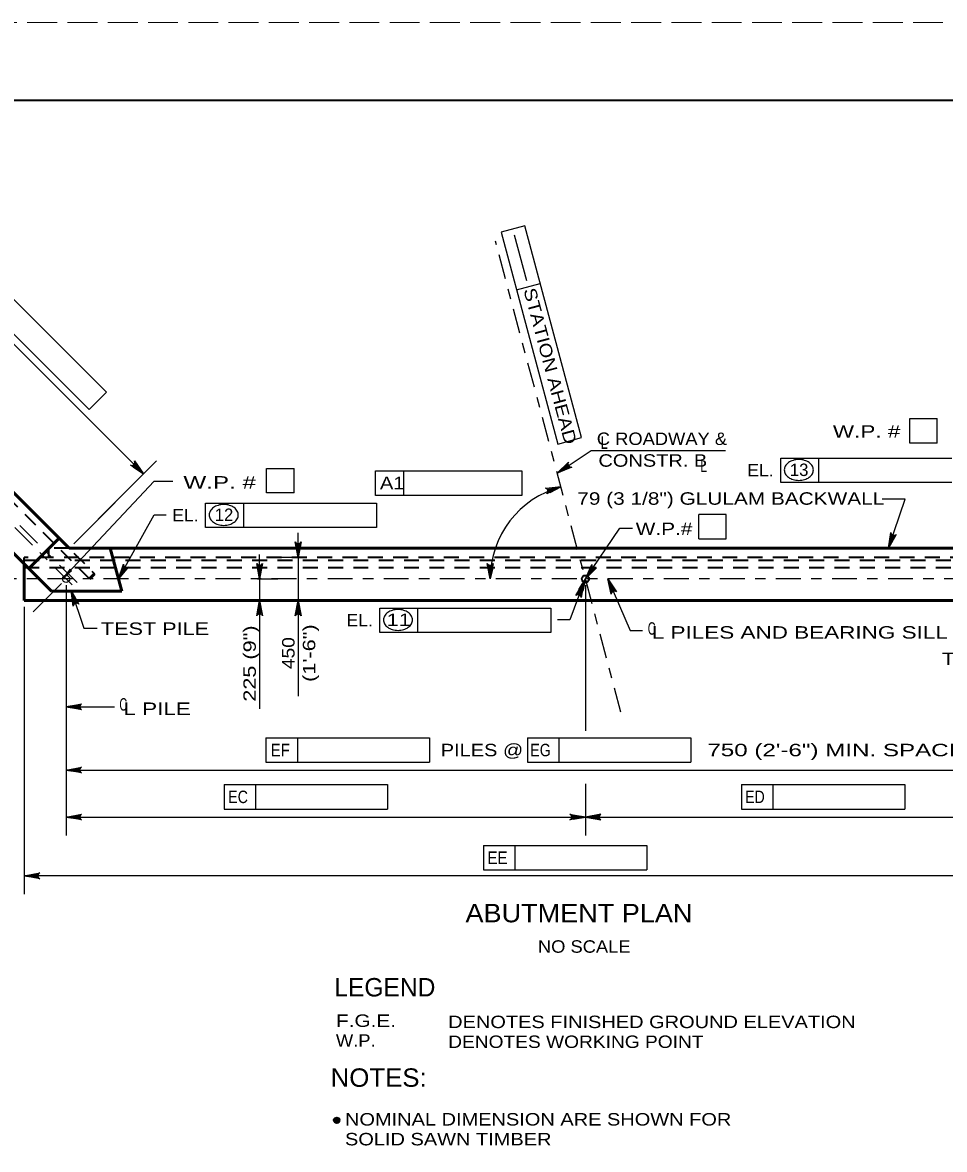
# Model space of a CAD drawing. Extents: x -6.4 to 73.1, y -66 to 0.
# Drawn here: x 42.06 to 50.94, y -10.86 to 0 of the extents above; entities that cross this region are included whole.
import ezdxf
from ezdxf.enums import TextEntityAlignment as Align

# ---------------------------------------------------------------- set-up
doc = ezdxf.new("R2010")
doc.units = 0
doc.header["$LTSCALE"] = 0.048
for name, pattern in [('DOT_DASHED', [7.7, 5, -1.2, 0.3, -1.2]), ('LONG_DASHED', [7.5, 6, -1.5]), ('MEDIUM_DASHED', [4.5, 3, -1.5])]:
    doc.linetypes.add(name, pattern=pattern)
for name, color, linetype, lineweight in [('1', 7, 'Continuous', 13), ('2', 7, 'Continuous', 53), ('3', 7, 'Continuous', 35), ('4', 7, 'Continuous', 25), ('5', 7, 'Continuous', 25), ('6', 7, 'DOT_DASHED', 25), ('63', 7, 'LONG_DASHED', 13)]:
    doc.layers.add(name, color=color, linetype=linetype, lineweight=lineweight)

msp = doc.modelspace()

# ---------------------------------------------------------------- hatches: boundary and pattern name
at = {"layer": '4'}
for points in [[(43.15342, -4.25192), (43.12558, -4.27975), (43.223, -4.34933)], [(47.29833, -4.26058), (47.32025, -4.29333), (47.21108, -4.3425)], [(47.13792, -4.53175), (47.12533, -4.49442), (47.2435, -4.47525)], [(50.40383, -5.06467), (50.451, -4.956), (50.43242, -4.94967)], [(44.69458, -5.03517), (44.734, -5.03517), (44.71433, -5.15325)], [(42.44258, -5.36), (42.53067, -5.28067), (42.51633, -5.26725)], [(43.021, -5.25075), (43.05542, -5.26975), (42.98108, -5.36358)], [(44.32292, -5.24183), (44.36225, -5.24183), (44.34258, -5.36)], [(46.55258, -5.24083), (46.59183, -5.24342), (46.56458, -5.36)], [(47.48233, -5.36), (47.55692, -5.26783), (47.54058, -5.25683)], [(47.4565, -5.47692), (47.41992, -5.46217), (47.48233, -5.36)], [(47.69683, -5.36), (47.735, -5.47225), (47.753, -5.46433)], [(42.52558, -5.47133), (42.55425, -5.58633), (42.57292, -5.58)], [(44.32292, -5.68475), (44.36225, -5.68475), (44.34258, -5.56667)], [(44.69458, -5.68475), (44.734, -5.68475), (44.71433, -5.56667)], [(42.59633, -6.61167), (42.59633, -6.57233), (42.47825, -6.592)], [(42.59633, -7.18158), (42.59633, -7.221), (42.47825, -7.20125)], [(42.59633, -7.63492), (42.59633, -7.67425), (42.47825, -7.65458)], [(47.36417, -7.63492), (47.36417, -7.67425), (47.48233, -7.65458)], [(47.60042, -7.63492), (47.60042, -7.67425), (47.48233, -7.65458)], [(42.19233, -8.20067), (42.19233, -8.24008), (42.07425, -8.22042)]]:
    msp.add_hatch(color=256, dxfattribs=at).paths.add_polyline_path(points)

# ---------------------------------------------------------------- linework, layer by layer
at = {"layer": '1', "lineweight": 35}
msp.add_lwpolyline([(35.75, -21.25), (67.25, -21.25), (67.25, -0.75), (35.75, -0.75)], close=True, dxfattribs=at)
at = {"layer": '2'}
for p, q in [((42.50767, -5.06467), (41.70775, -4.26483)), ((42.33642, -5.47808), (41.4155, -4.55708)), ((42.41025, -4.96725), (42.11792, -5.25958)), ((52.37042, -5.06467), (42.50767, -5.06467)), ((42.90358, -5.06467), (43.01383, -5.47808)), ((42.07425, -5.56667), (42.07425, -5.21583)), ((42.70317, -5.36), (42.75192, -5.31125)), ((43.01383, -5.47808), (42.33642, -5.47808)), ((52.84975, -5.56667), (42.07425, -5.56667))]:
    msp.add_line(p, q, dxfattribs=at)
at = {"layer": '3', "linetype": 'MEDIUM_DASHED'}
for p, q in [((42.70317, -5.36), (41.65908, -4.3135)), ((42.31217, -5.15325), (42.31217, -5.06467)), ((42.50767, -5.06467), (42.31217, -5.06467)), ((52.84975, -5.15325), (42.07425, -5.15325)), ((42.07425, -5.17967), (52.84975, -5.17967)), ((42.55367, -5.11067), (42.75192, -5.31125)), ((42.07425, -5.24858), (52.84975, -5.24858))]:
    msp.add_line(p, q, dxfattribs=at)
at = {"layer": '3'}
msp.add_line((42.07425, -5.21583), (42.07425, -5.15325), dxfattribs=at)
msp.add_circle((47.48232, -5.35998), 0.03402, dxfattribs=at)
at = {"layer": '4'}
for p, q in [((43.223, -4.34933), (40.84933, -1.97567)), ((46.89733, -1.9575), (46.66917, -2.01867)), ((46.66917, -2.01867), (47.21625, -4.06042)), ((46.91658, -2.48725), (46.79933, -2.04958)), ((47.44442, -3.99925), (46.89742, -1.9575)), ((41.6635, -2.35983), (42.86617, -3.5625)), ((41.4965, -2.52683), (42.69908, -3.7295)), ((46.81833, -2.57525), (47.0465, -2.51408)), ((42.86617, -3.5625), (42.69908, -3.7295)), ((50.8725, -4.05125), (50.8725, -3.81508)), ((47.21625, -4.06042), (47.44442, -3.99925)), ((47.21108, -4.34258), (47.53908, -4.12342)), ((47.53908, -4.12342), (48.831, -4.12342)), ((50.8725, -4.05125), (50.60883, -4.05125)), ((42.55117, -5.02117), (43.34825, -4.22408)), ((49.36392, -4.19658), (51.01225, -4.19658)), ((49.36392, -4.43283), (49.36392, -4.19658)), ((49.73075, -4.43283), (49.73075, -4.19658)), ((44.41058, -4.29517), (44.67425, -4.29517)), ((44.67425, -4.53142), (44.67425, -4.29517)), ((45.45883, -4.319), (46.87083, -4.319)), ((45.45883, -4.55525), (45.45883, -4.319)), ((45.73258, -4.55525), (45.73258, -4.319)), ((46.87083, -4.319), (46.87083, -4.55525)), ((51.01225, -4.43283), (49.36392, -4.43283)), ((42.55117, -5.02117), (43.01925, -4.55308)), ((46.87083, -4.55525), (45.45883, -4.55525)), ((43.82217, -4.62983), (45.47058, -4.62983)), ((43.82217, -4.86608), (43.82217, -4.62983)), ((44.189, -4.86608), (44.189, -4.62983)), ((45.47058, -4.62983), (45.47058, -4.86608)), ((42.98258, -5.36092), (43.32508, -4.74142)), ((43.32508, -4.74142), (43.44325, -4.74142)), ((48.839, -4.73858), (48.57533, -4.73858)), ((48.57533, -4.97483), (48.57533, -4.73858)), ((48.839, -4.97483), (48.839, -4.73858)), ((45.47058, -4.86608), (43.82217, -4.86608)), ((44.71433, -5.03517), (44.71433, -4.91708)), ((48.57533, -4.97483), (48.839, -4.97483)), ((44.34258, -5.24183), (44.34258, -5.12375)), ((44.6915, -5.15325), (44.53717, -5.15325)), ((44.71433, -5.15325), (44.71433, -5.56667)), ((42.43475, -5.4035), (42.16058, -5.67758)), ((42.47825, -5.4215), (42.47825, -7.83175)), ((44.32258, -5.36), (44.51975, -5.36)), ((44.34258, -5.36), (44.34258, -5.56667)), ((47.46758, -5.39067), (47.33242, -5.75308)), ((47.48233, -5.4215), (47.48233, -6.82475)), ((42.07425, -5.62817), (42.07425, -8.39758)), ((44.32258, -5.56667), (44.51975, -5.56667)), ((44.6915, -5.56667), (44.53717, -5.56667)), ((45.50117, -5.64158), (47.1495, -5.64158)), ((45.50117, -5.87775), (45.50117, -5.64158)), ((45.868, -5.87775), (45.868, -5.64158)), ((47.1495, -5.64158), (47.1495, -5.87775)), ((44.34258, -5.68475), (44.34258, -6.61192)), ((44.71433, -5.68475), (44.71433, -6.48883)), ((47.33242, -5.75308), (47.21425, -5.75308)), ((47.1495, -5.87775), (45.50117, -5.87775)), ((42.47825, -6.592), (42.94283, -6.592)), ((44.40375, -6.89058), (44.40375, -7.12683)), ((44.40375, -6.89058), (45.9785, -6.89058)), ((44.70617, -6.89058), (44.70617, -7.12683)), ((45.9785, -6.89058), (45.9785, -7.12683)), ((46.92433, -6.89058), (48.49917, -6.89058)), ((46.92433, -6.89058), (46.92433, -7.12683)), ((47.22675, -6.89058), (47.22675, -7.12683)), ((48.49917, -6.89058), (48.49917, -7.12683)), ((44.40375, -7.12683), (45.9785, -7.12683)), ((46.92433, -7.12683), (48.49917, -7.12683)), ((42.47825, -7.20125), (52.39958, -7.20133)), ((44.00158, -7.34175), (45.57642, -7.34175)), ((44.00158, -7.34175), (44.00158, -7.578)), ((44.304, -7.34175), (44.304, -7.578)), ((45.57642, -7.34175), (45.57642, -7.578)), ((47.48233, -7.334), (47.48233, -7.83175)), ((48.98658, -7.34175), (50.56142, -7.34175)), ((48.98658, -7.34175), (48.98658, -7.578)), ((49.28908, -7.34175), (49.28908, -7.578)), ((50.56142, -7.34175), (50.56142, -7.578)), ((44.00158, -7.578), (45.57642, -7.578)), ((48.98658, -7.578), (50.56142, -7.578)), ((42.47825, -7.65458), (47.36417, -7.65458)), ((47.60042, -7.65458), (52.39958, -7.65458)), ((46.49892, -7.92767), (48.07375, -7.92767)), ((46.49892, -7.92767), (46.49892, -8.16383)), ((46.80142, -7.92767), (46.80142, -8.16383)), ((48.07375, -7.92767), (48.07375, -8.16383)), ((52.84975, -8.22042), (42.07425, -8.22042)), ((46.49892, -8.16383), (48.07375, -8.16383))]:
    msp.add_line(p, q, dxfattribs=at)
at = {"layer": '4', "linetype": 'DOT_DASHED'}
for p, q in [((42.53525, -5.417), (41.53792, -4.41967)), ((42.58425, -5.39617), (41.59467, -4.40667)), ((53.33858, -5.36), (41.53183, -5.36))]:
    msp.add_line(p, q, dxfattribs=at)
at = {"layer": '4'}
for points in [[(50.60883, -4.05125), (50.60883, -3.81508), (50.8725, -3.81508)], [(43.223, -4.34933), (43.09775, -4.26367), (43.1115, -4.26617), (43.12283, -4.26325), (43.13108, -4.25742), (43.13692, -4.24917), (43.13983, -4.23783), (43.13733, -4.22408), (43.223, -4.34933), (43.13983, -4.23783), (43.13692, -4.24917), (43.223, -4.34933), (43.13108, -4.25742), (43.12283, -4.26325), (43.223, -4.34933), (43.1115, -4.26617)], [(44.67425, -4.53142), (44.41058, -4.53142), (44.41058, -4.29517)], [(47.21108, -4.34258), (47.31958, -4.2365), (47.31442, -4.2495), (47.31508, -4.26108), (47.31917, -4.27033), (47.32617, -4.27775), (47.33667, -4.28275), (47.35058, -4.283), (47.21108, -4.34258), (47.33667, -4.28275), (47.32617, -4.27775), (47.21108, -4.34258), (47.31917, -4.27033), (47.31508, -4.26108), (47.21108, -4.34258), (47.31442, -4.2495)], [(42.44258, -5.36), (43.32783, -4.41908), (43.50767, -4.41908)], [(47.24625, -4.4745), (47.10925, -4.53967), (47.11833, -4.529), (47.1215, -4.51783), (47.12058, -4.50775), (47.11633, -4.4985), (47.10808, -4.49033), (47.09492, -4.48558), (47.24625, -4.4745), (47.10808, -4.49033), (47.11633, -4.4985), (47.24625, -4.4745), (47.12058, -4.50775), (47.1215, -4.51783), (47.24625, -4.4745), (47.11833, -4.529)], [(50.40383, -5.06467), (50.56333, -4.59325), (50.34317, -4.59325)], [(47.48233, -5.36), (47.81508, -4.87083), (47.936, -4.87083)], [(50.40383, -5.06467), (50.42517, -4.91442), (50.429, -4.92792), (50.43658, -4.93667), (50.4455, -4.9415), (50.4555, -4.94308), (50.46692, -4.94067), (50.47808, -4.93233), (50.40383, -5.06467), (50.46692, -4.94067), (50.4555, -4.94308), (50.40383, -5.06467), (50.4455, -4.9415), (50.43658, -4.93667), (50.40383, -5.06467), (50.429, -4.92792)], [(44.71433, -5.15325), (44.68633, -5.00408), (44.69433, -5.01558), (44.70433, -5.0215), (44.71433, -5.02325), (44.72433, -5.0215), (44.73433, -5.01558), (44.74233, -5.00408), (44.71433, -5.15325), (44.73433, -5.01558), (44.72433, -5.0215), (44.71433, -5.15325), (44.71433, -5.02325), (44.70433, -5.0215), (44.71433, -5.15325), (44.69433, -5.01558)], [(44.34258, -5.36), (44.31458, -5.21083), (44.32258, -5.22233), (44.33258, -5.22825), (44.34258, -5.23), (44.35258, -5.22825), (44.36258, -5.22233), (44.37058, -5.21083), (44.34258, -5.36), (44.36258, -5.22233), (44.35258, -5.22825), (44.34258, -5.36), (44.34258, -5.23), (44.33258, -5.22825), (44.34258, -5.36), (44.32258, -5.22233)], [(46.56458, -5.36), (46.53658, -5.21083), (46.54458, -5.22233), (46.55458, -5.22825), (46.56458, -5.23), (46.57458, -5.22825), (46.58458, -5.22233), (46.59258, -5.21083), (46.56458, -5.36), (46.58458, -5.22233), (46.57458, -5.22825), (46.56458, -5.36), (46.56458, -5.23), (46.55458, -5.22825), (46.56458, -5.36), (46.54458, -5.22233)], [(42.98258, -5.36092), (43.03025, -5.21683), (43.03167, -5.23075), (43.03758, -5.24083), (43.0455, -5.24717), (43.05508, -5.2505), (43.06667, -5.25017), (43.07925, -5.24392), (42.98258, -5.36092), (43.06667, -5.25017), (43.05508, -5.2505), (42.98258, -5.36092), (43.0455, -5.24717), (43.03758, -5.24083), (42.98258, -5.36092), (43.03167, -5.23075)], [(47.48233, -5.36), (47.54308, -5.221), (47.54325, -5.23492), (47.54817, -5.2455), (47.55542, -5.2525), (47.56467, -5.25675), (47.57625, -5.25742), (47.58933, -5.25242), (47.48233, -5.36), (47.57625, -5.25742), (47.56467, -5.25675), (47.48233, -5.36), (47.55542, -5.2525), (47.54817, -5.2455), (47.48233, -5.36), (47.54325, -5.23492)], [(47.46758, -5.39067), (47.44167, -5.54017), (47.43825, -5.52658), (47.43092, -5.51758), (47.42217, -5.5125), (47.41217, -5.51058), (47.40075, -5.51267), (47.38925, -5.52067), (47.46758, -5.39067), (47.40075, -5.51267), (47.41217, -5.51058), (47.46758, -5.39067), (47.42217, -5.5125), (47.43092, -5.51758), (47.46758, -5.39067), (47.43825, -5.52658)], [(47.69683, -5.36), (47.91358, -5.85817), (48.03158, -5.85817)], [(47.69683, -5.36), (47.782, -5.48558), (47.77008, -5.47825), (47.75858, -5.47675), (47.74867, -5.47917), (47.74025, -5.48475), (47.73342, -5.49417), (47.73067, -5.50792), (47.69683, -5.36), (47.73342, -5.49417), (47.74025, -5.48475), (47.69683, -5.36), (47.74867, -5.47917), (47.75858, -5.47675), (47.69683, -5.36), (47.77008, -5.47825)], [(42.52558, -5.47133), (42.64967, -5.83608), (42.7785, -5.83608)], [(42.52558, -5.47133), (42.60008, -5.6035), (42.58883, -5.59517), (42.5775, -5.59283), (42.56742, -5.59442), (42.5585, -5.59925), (42.551, -5.60808), (42.54717, -5.6215), (42.52558, -5.47133), (42.551, -5.60808), (42.5585, -5.59925), (42.52558, -5.47133), (42.56742, -5.59442), (42.5775, -5.59283), (42.52558, -5.47133), (42.58883, -5.59517)], [(44.34258, -5.56667), (44.37058, -5.71583), (44.36258, -5.70433), (44.35258, -5.69842), (44.34258, -5.69667), (44.33258, -5.69842), (44.32258, -5.70433), (44.31458, -5.71583), (44.34258, -5.56667), (44.32258, -5.70433), (44.33258, -5.69842), (44.34258, -5.56667), (44.34258, -5.69667), (44.35258, -5.69842), (44.34258, -5.56667), (44.36258, -5.70433)], [(44.71433, -5.56667), (44.74233, -5.71583), (44.73433, -5.70433), (44.72433, -5.69842), (44.71433, -5.69667), (44.70433, -5.69842), (44.69433, -5.70433), (44.68633, -5.71583), (44.71433, -5.56667), (44.69433, -5.70433), (44.70433, -5.69842), (44.71433, -5.56667), (44.71433, -5.69667), (44.72433, -5.69842), (44.71433, -5.56667), (44.73433, -5.70433)], [(42.47825, -6.592), (42.62742, -6.564), (42.61592, -6.572), (42.61, -6.582), (42.60825, -6.592), (42.61, -6.602), (42.61592, -6.612), (42.62742, -6.62), (42.47825, -6.592), (42.61592, -6.612), (42.61, -6.602), (42.47825, -6.592), (42.60825, -6.592), (42.61, -6.582), (42.47825, -6.592), (42.61592, -6.572)], [(42.47825, -7.20125), (42.62742, -7.17325), (42.61592, -7.18125), (42.61, -7.19125), (42.60825, -7.20125), (42.61, -7.21125), (42.61592, -7.22125), (42.62742, -7.22925), (42.47825, -7.20125), (42.61592, -7.22125), (42.61, -7.21125), (42.47825, -7.20125), (42.60825, -7.20125), (42.61, -7.19125), (42.47825, -7.20125), (42.61592, -7.18125)], [(42.47825, -7.65458), (42.62742, -7.62658), (42.61592, -7.63458), (42.61, -7.64458), (42.60825, -7.65458), (42.61, -7.66458), (42.61592, -7.67458), (42.62742, -7.68258), (42.47825, -7.65458), (42.61592, -7.67458), (42.61, -7.66458), (42.47825, -7.65458), (42.60825, -7.65458), (42.61, -7.64458), (42.47825, -7.65458), (42.61592, -7.63458)], [(47.48233, -7.65458), (47.33317, -7.68258), (47.34467, -7.67458), (47.35058, -7.66458), (47.35233, -7.65458), (47.35058, -7.64458), (47.34467, -7.63458), (47.33317, -7.62658), (47.48233, -7.65458), (47.34467, -7.63458), (47.35058, -7.64458), (47.48233, -7.65458), (47.35233, -7.65458), (47.35058, -7.66458), (47.48233, -7.65458), (47.34467, -7.67458)], [(47.48233, -7.65458), (47.6315, -7.68258), (47.62, -7.67458), (47.61408, -7.66458), (47.61233, -7.65458), (47.61408, -7.64458), (47.62, -7.63458), (47.6315, -7.62658), (47.48233, -7.65458), (47.62, -7.63458), (47.61408, -7.64458), (47.48233, -7.65458), (47.61233, -7.65458), (47.61408, -7.66458), (47.48233, -7.65458), (47.62, -7.67458)], [(42.07425, -8.22042), (42.22342, -8.19242), (42.21192, -8.20042), (42.206, -8.21042), (42.20425, -8.22042), (42.206, -8.23042), (42.21192, -8.24042), (42.22342, -8.24842), (42.07425, -8.22042), (42.21192, -8.24042), (42.206, -8.23042), (42.07425, -8.22042), (42.20425, -8.22042), (42.206, -8.21042), (42.07425, -8.22042), (42.21192, -8.20042)]]:
    msp.add_lwpolyline(points, dxfattribs=at)
for points in [[(43.15342, -4.25192), (43.12558, -4.27975), (43.223, -4.34933)], [(47.29833, -4.26058), (47.32025, -4.29333), (47.21108, -4.3425)], [(47.13792, -4.53175), (47.12533, -4.49442), (47.2435, -4.47525)], [(50.40383, -5.06467), (50.451, -4.956), (50.43242, -4.94967)], [(44.69458, -5.03517), (44.734, -5.03517), (44.71433, -5.15325)], [(42.44258, -5.36), (42.53067, -5.28067), (42.51633, -5.26725)], [(43.021, -5.25075), (43.05542, -5.26975), (42.98108, -5.36358)], [(44.32292, -5.24183), (44.36225, -5.24183), (44.34258, -5.36)], [(46.55258, -5.24083), (46.59183, -5.24342), (46.56458, -5.36)], [(47.48233, -5.36), (47.55692, -5.26783), (47.54058, -5.25683)], [(47.4565, -5.47692), (47.41992, -5.46217), (47.48233, -5.36)], [(47.69683, -5.36), (47.735, -5.47225), (47.753, -5.46433)], [(42.52558, -5.47133), (42.55425, -5.58633), (42.57292, -5.58)], [(44.32292, -5.68475), (44.36225, -5.68475), (44.34258, -5.56667)], [(44.69458, -5.68475), (44.734, -5.68475), (44.71433, -5.56667)], [(42.59633, -6.61167), (42.59633, -6.57233), (42.47825, -6.592)], [(42.59633, -7.18158), (42.59633, -7.221), (42.47825, -7.20125)], [(42.59633, -7.63492), (42.59633, -7.67425), (42.47825, -7.65458)], [(47.36417, -7.63492), (47.36417, -7.67425), (47.48233, -7.65458)], [(47.60042, -7.63492), (47.60042, -7.67425), (47.48233, -7.65458)], [(42.19233, -8.20067), (42.19233, -8.24008), (42.07425, -8.22042)]]:
    msp.add_lwpolyline(points, close=True, dxfattribs=at)
msp.add_circle((42.47824, -5.35998), 0.03402, dxfattribs=at)
at = {"layer": '4', "lineweight": 35}
for radius in [0.02667, 0.02, 0.01333, 0.00667]:
    msp.add_circle((45.08607, -10.57529), radius, dxfattribs=at)
at = {"layer": '4'}
for centre, radius, start, end in [((49.5252, -4.35842), 0.14646, 106.53583, 125.63164), ((49.53897, -4.40482), 0.19487, 90, 106.53583), ((49.53897, -4.40482), 0.19487, 73.46417, 90), ((49.55275, -4.35842), 0.14646, 54.36836, 73.46417), ((49.47192, -4.31041), 0.07309, 149.97668, 180), ((49.47192, -4.31041), 0.07309, 180, 210.02332), ((49.50413, -4.32903), 0.1103, 125.63164, 149.97668), ((49.57382, -4.32903), 0.1103, 30.02332, 54.36836), ((49.60603, -4.31041), 0.07309, 0, 30.02332), ((49.60603, -4.31041), 0.07309, 329.97668, 0), ((49.50413, -4.2918), 0.1103, 210.02332, 234.36836), ((49.5252, -4.26241), 0.14646, 234.36836, 253.46417), ((49.53897, -4.216), 0.19487, 253.46417, 270), ((49.53897, -4.216), 0.19487, 270, 286.53583), ((49.55275, -4.26241), 0.14646, 286.53583, 305.63164), ((49.57382, -4.2918), 0.1103, 305.63164, 329.97668), ((47.48056, -5.35999), 0.91598, 104.82219, 180.00094), ((43.98348, -4.7917), 0.14646, 106.53583, 125.63164), ((43.99726, -4.83811), 0.19487, 90, 106.53583), ((43.99726, -4.83811), 0.19487, 73.46417, 90), ((44.01104, -4.7917), 0.14646, 54.36836, 73.46417), ((43.93021, -4.74369), 0.07309, 149.97668, 180), ((43.93021, -4.74369), 0.07309, 180, 210.02332), ((43.96242, -4.76231), 0.1103, 125.63164, 149.97668), ((44.03211, -4.76231), 0.1103, 30.02332, 54.36836), ((44.06432, -4.74369), 0.07309, 0, 30.02332), ((44.06432, -4.74369), 0.07309, 329.97668, 0), ((43.96242, -4.72508), 0.1103, 210.02332, 234.36836), ((43.98348, -4.69569), 0.14646, 234.36836, 253.46417), ((43.99726, -4.64928), 0.19487, 253.46417, 270), ((43.99726, -4.64928), 0.19487, 270, 286.53583), ((44.01104, -4.69569), 0.14646, 286.53583, 305.63164), ((44.03211, -4.72508), 0.1103, 305.63164, 329.97668), ((45.60919, -5.75538), 0.07309, 149.97668, 180), ((45.6414, -5.774), 0.1103, 125.63164, 149.97668), ((45.66247, -5.80339), 0.14646, 106.53583, 125.63164), ((45.67624, -5.8498), 0.19487, 90, 106.53583), ((45.67624, -5.8498), 0.19487, 73.46417, 90), ((45.69002, -5.80339), 0.14646, 54.36836, 73.46417), ((45.71109, -5.774), 0.1103, 30.02332, 54.36836), ((45.7433, -5.75538), 0.07309, 0, 30.02332), ((45.60919, -5.75538), 0.07309, 180, 210.02332), ((45.6414, -5.73677), 0.1103, 210.02332, 234.36836), ((45.66247, -5.70738), 0.14646, 234.36836, 253.46417), ((45.67624, -5.66097), 0.19487, 253.46417, 270), ((45.67624, -5.66097), 0.19487, 270, 286.53583), ((45.69002, -5.70738), 0.14646, 286.53583, 305.63164), ((45.71109, -5.73677), 0.1103, 305.63164, 329.97668), ((45.7433, -5.75538), 0.07309, 329.97668, 0)]:
    msp.add_arc(centre, radius, start, end, dxfattribs=at)
at = {"layer": '6'}
msp.add_line((47.82483, -6.64492), (46.61467, -2.10533), dxfattribs=at)
at = {"layer": '63'}
msp.add_lwpolyline([(34, -22), (68, -22), (68, 0), (34, 0)], close=True, dxfattribs=at)

# ---------------------------------------------------------------- texts
at = {"layer": '4', "width": 1.2}
msp.add_text('STATION AHEAD', height=0.12, rotation=285, dxfattribs=at).set_placement((47.08499, -3.32451), align=Align.CENTER)
at = {"layer": '4'}
for s, height, width, p in [('W.P. #', 0.12, 1.35, (50.19204, -3.99942)), ('W.P. # ', 0.12, 1.45, (43.99012, -4.49)), ('A1', 0.12, 1.2, (45.62037, -4.49583)), ('11', 0.12, 1.3, (45.68354, -5.81383)), ('PILES @', 0.12, 1.2, (46.48554, -7.06875)), ('EG', 0.12, 0.85, (47.04992, -7.06875)), ('EF', 0.12, 0.9, (44.542, -7.06875)), ('EC', 0.12, 0.85, (44.13542, -7.51992)), ('ED', 0.12, 0.85, (49.11567, -7.51992)), ('EE', 0.12, 0.9, (46.63504, -8.10583)), ('ABUTMENT PLAN', 0.1772, 1.1, (47.42017, -8.66825)), ('NO SCALE', 0.12, 1.1, (47.47104, -8.96158))]:
    msp.add_text(s, height=height, dxfattribs=dict(at, width=width)).set_placement(p, align=Align.CENTER)
for s, height, width, p in [('C ROADWAY &', 0.12, 1.1, (47.59208, -4.06983)), ('L', 0.12, 0.75, (47.63042, -4.10717)), ('CONSTR. B', 0.12, 1.2, (47.60758, -4.27925)), ('L', 0.12, 0.75, (48.5885, -4.331)), ('EL.', 0.12, 1.05, (49.04308, -4.37342)), ('EL.', 0.12, 1.05, (43.50142, -4.80675)), ('W.P.#', 0.12, 1.25, (47.96717, -4.93742)), ('EL.', 0.12, 1.05, (45.18033, -5.81842)), ('TEST PILE', 0.12, 1.3, (42.81283, -5.8995)), ('C', 0.12, 0.65, (48.08325, -5.89767)), ('L PILES AND BEARING SILL', 0.12, 1.35, (48.12158, -5.93533)), ('TEST PILE', 0.12, 1.3, (50.916, -6.19075)), ('C', 0.12, 0.65, (42.99125, -6.62908)), ('L PILE', 0.12, 1.35, (43.02992, -6.67067)), ('750 (2\'-6") MIN. SPACING', 0.12, 1.45, (48.65742, -7.06875)), ('NOTES:', 0.1772, 1.05, (45.02675, -10.25292)), ('NOMINAL DIMENSION ARE SHOWN FOR ', 0.12, 1.2, (45.16525, -10.62625)), ('SOLID SAWN TIMBER', 0.12, 1.2, (45.16525, -10.81742))]:
    msp.add_text(s, height=height, dxfattribs=dict(at, width=width)).set_placement(p)
for s, p in [('13', (49.54204, -4.36892)), ('12', (43.99963, -4.80217))]:
    msp.add_text(s, height=0.12, dxfattribs=at).set_placement(p, align=Align.CENTER)
at = {"layer": '5'}
for s, width, p in [('79 (3 1/8") GLULAM BACKWALL', 1.25, (47.40392, -4.6455)), ('F.G.E.', 1.25, (45.078, -9.67617)), ('DENOTES FINISHED GROUND ELEVATION', 1.2, (46.15958, -9.68775)), ('W.P.', 1.1, (45.078, -9.86733)), ('DENOTES WORKING POINT', 1.15, (46.15958, -9.879))]:
    msp.add_text(s, height=0.12, dxfattribs=dict(at, width=width)).set_placement(p)
for s, width, p in [('225 (9")', 1.3, (44.30617, -6.17596)), ('(1\'-6")', 1.3, (44.87917, -6.07512)), ('450', 1.15, (44.67917, -6.07512))]:
    msp.add_text(s, height=0.12, rotation=90, dxfattribs=dict(at, width=width)).set_placement(p, align=Align.CENTER)
msp.add_text('LEGEND', height=0.1772, dxfattribs=at).set_placement((45.06217, -9.3825))

doc.saveas('drawing.dxf')
